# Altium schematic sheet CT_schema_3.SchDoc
size 400 x 230 mm
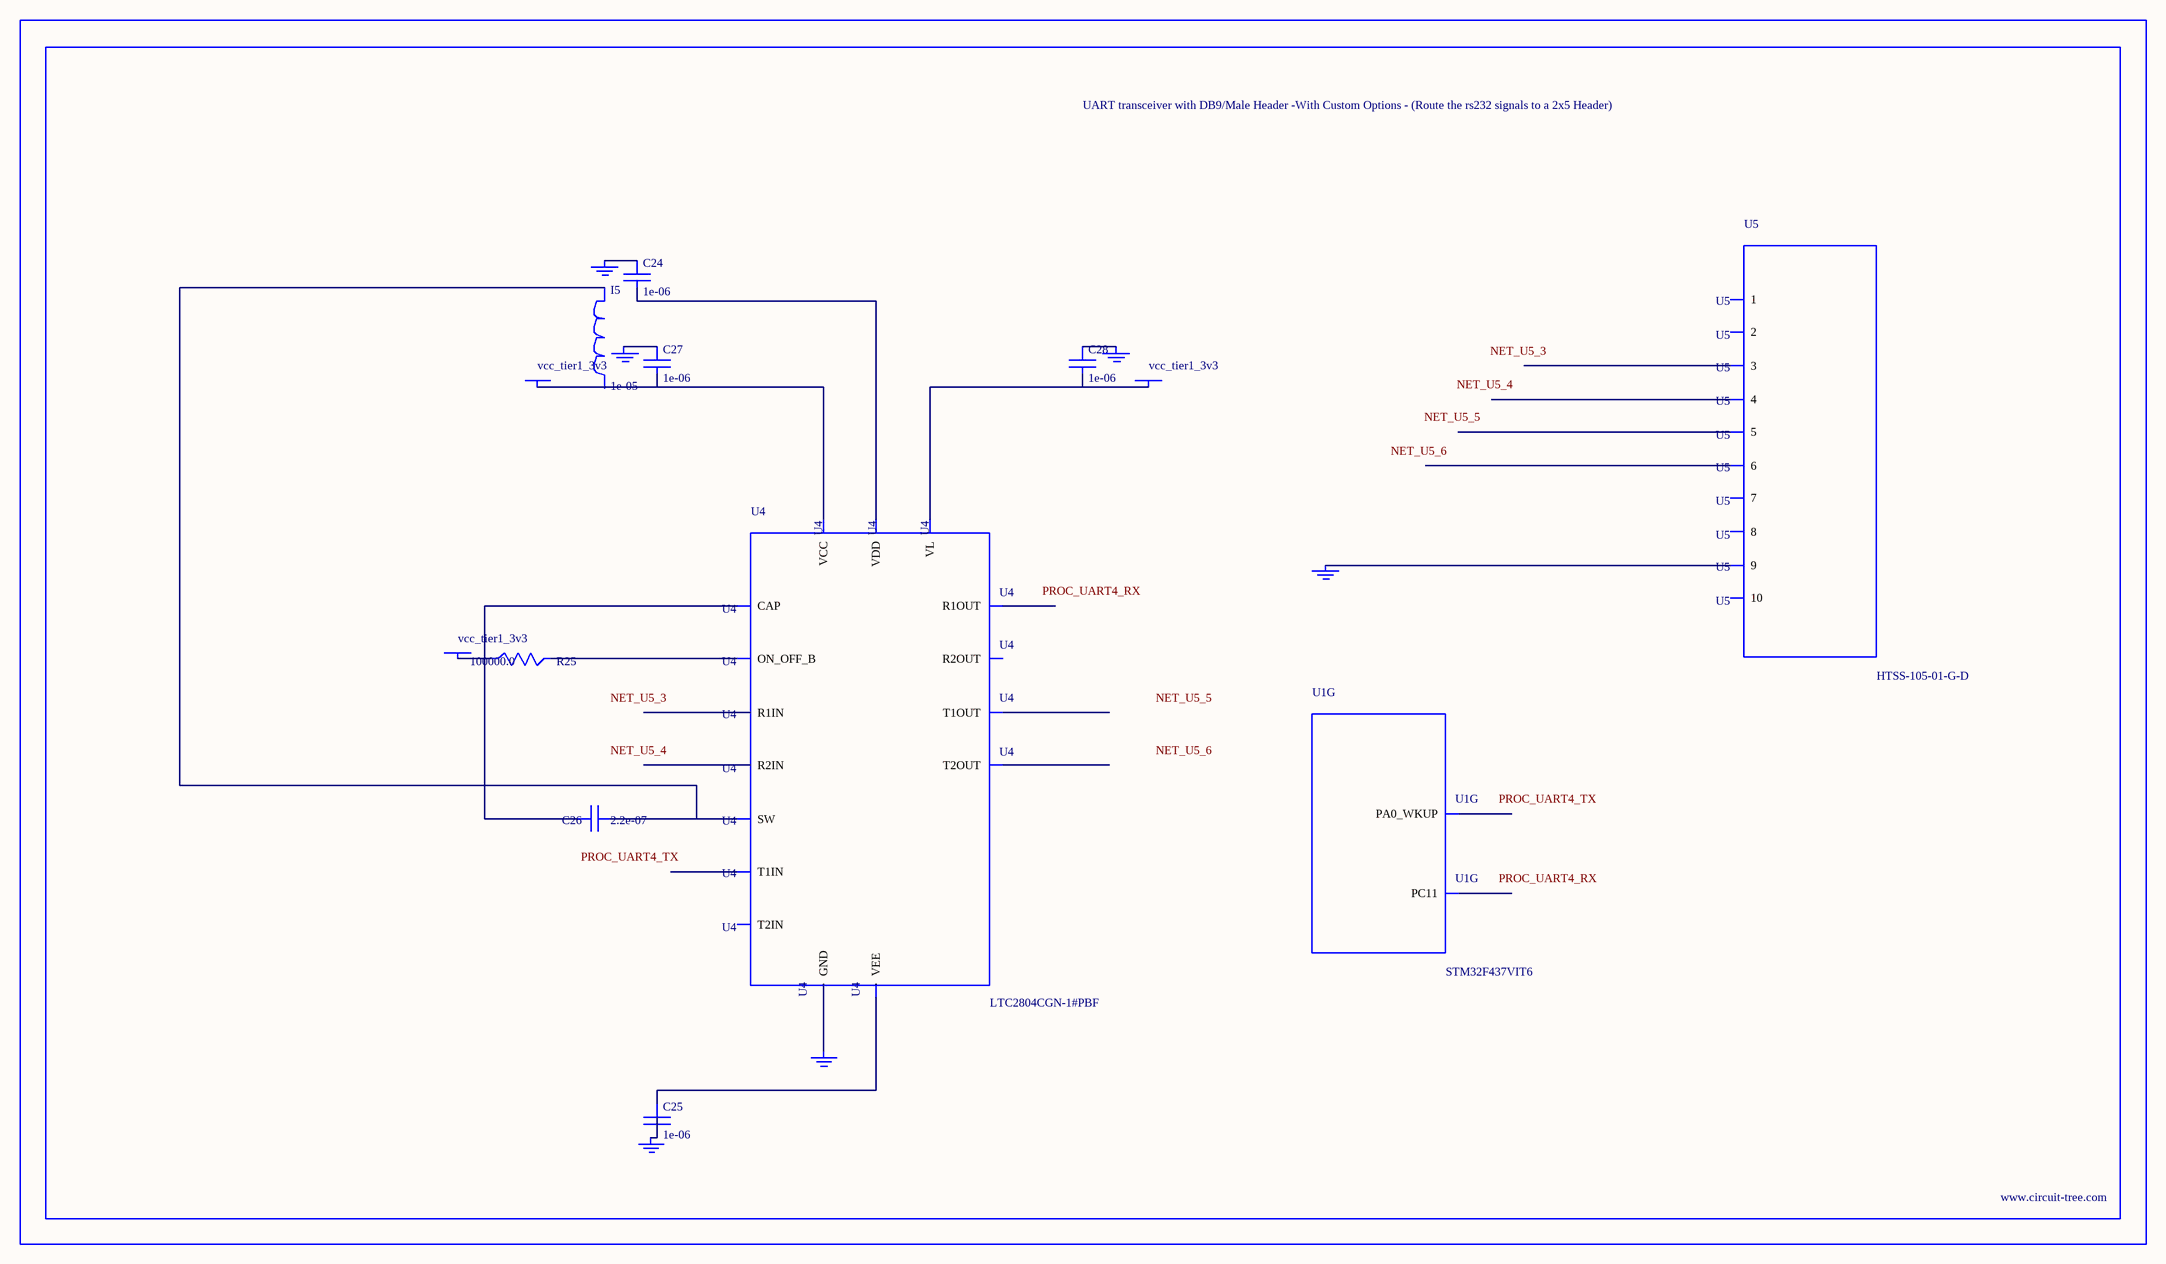
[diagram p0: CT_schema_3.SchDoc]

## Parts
BORDER2  (no value)
C24  1e-06  [C0603]
C25  1e-06  [C0603]
C26  2.2e-07  [C0603]
C27  1e-06  [C0603]
C28  1e-06  [C0603]
GND_INSTANCE_2_0  (no value)
GND_INSTANCE_2_1  (no value)
GND_INSTANCE_2_2  (no value)
GND_INSTANCE_2_3  (no value)
GND_INSTANCE_2_4  (no value)
GND_INSTANCE_2_5  (no value)
I5  1e-05  [L1210]
POWER_INSTANCE_2_0  vcc_tier1_3v3
POWER_INSTANCE_2_1  vcc_tier1_3v3
POWER_INSTANCE_2_2  vcc_tier1_3v3
R25  100000.0  [R0603]
U1  STM32F437VIT6  [LQFP100]  (part G of 9)
U4  LTC2804CGN-1#PBF  [SSOP-16]
U5  HTSS-105-01-G-D  [HTSS-105-01-G-D]

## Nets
NetC24_1: C24.1 GND_INSTANCE_2_1.0(GND)
NetC24_2: C24.2 U4.6(VDD)
NetC25_1: C25.1 U4.9(VEE)
NetC25_2: C25.2 GND_INSTANCE_2_2.0(GND)
NetC26_1: C26.1 I5.1 U4.7(SW)
NetC26_2: C26.2 U4.10(CAP)
NetC27_1: C27.1 GND_INSTANCE_2_0.0(GND)
NetC27_2: C27.2 POWER_INSTANCE_2_0.0(PWR) U4.5(VCC)
NetC28_1: C28.1 GND_INSTANCE_2_3.0(GND)
NetC28_2: C28.2 POWER_INSTANCE_2_2.0(PWR) U4.12(VL)
NetGND_INSTANCE_2_4_0: GND_INSTANCE_2_4.0(GND) U4.8(GND)
NetGND_INSTANCE_2_5_0: GND_INSTANCE_2_5.0(GND) U5.9
NetPOWER_INSTANCE_2_1_0: POWER_INSTANCE_2_1.0(PWR) R25.1
NetR25_2: R25.2 U4.11(ON_OFF_B)

Not connected (* = marked no-connect by the designer): I5 2; U1 23(PA0_WKUP) 79(PC11); U4 1(R1IN) 2(R2IN) 3(T1OUT) 4(T2OUT) 13(T2IN) 14(T1IN) 15(R2OUT) 16(R1OUT); U5 1 2 3 4 5 6 7 8 10

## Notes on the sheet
- Labels drawn without touching a wire or pin: NET_U5_3, NET_U5_4, NET_U5_5, NET_U5_6, PROC_UART4_RX, PROC_UART4_TX

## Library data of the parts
BORDER2 = BORDER_PAGE2
C24 C25 C27 C28 = C0603C105K3RACTU
C26 = C0603C224K3RAC
GND_INSTANCE_2_0-GND_INSTANCE_2_5 = GND
I5 = CBC3225T100MR
POWER_INSTANCE_2_0-POWER_INSTANCE_2_2 = PWR
R25 = RC0603JR-07100KL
